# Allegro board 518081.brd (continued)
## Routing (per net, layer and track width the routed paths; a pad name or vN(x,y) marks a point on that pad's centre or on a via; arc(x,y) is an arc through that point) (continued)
MII0_TXP1: length 18.4
  TOP w0.104: P0.1 19.23,11.37 19.23,11.96 19.34,12.06 21.66,12.06 26.16,16.57 26.16,19.56 26.57,19.97 27.4,19.97 R12.1 28.6,20.09 29.77,20.09 29.93,19.94 U6.12
MII1_RXM1: length 15.5
  TOP w0.104: U3.9 29.69,36.68 28.68,37.68 28.48,37.68 R2.1 27.41,37.7 26,37.7 25.05,38.64 21.88,38.64 21.56,38.96 18.96,38.96 18.57,38.58 18.57,38.25 18.41,38.1 17.91,38.1 P1.8
MII1_RXP1: length 15.2
  TOP w0.104: U3.10 29.86,36.18 28.59,37.45 28.44,37.45 R3.1 27.43,37.47 25.9,37.47 24.96,38.41 21.78,38.41 21.46,38.73 19.05,38.73 18.8,38.48 18.8,37.85 19.18,37.47 P1.7
MII1_TXM1: length 15.8
  TOP w0.104: P1.2 17.65,30.73 18.8,30.73 19.3,31.24 21.77,31.24 25.97,35.44 27.44,35.44 R4.1 28.32,35.56 29.81,35.56 29.93,35.68 U3.11
MII1_TXP1: length 15
  TOP w0.104: U3.12 29.93,35.18 29.77,35.33 28.6,35.33 R5.1 27.4,35.21 26.07,35.21 21.87,31.01 19.4,31.01 19.23,30.85 19.23,30.42 P1.1
P_CONF[2]: length 5.2
  TOP w0.305: U5.E3 v2(53.67,28.6)
  BOTTOM w0.127: v2(53.67,28.6) 54.06,28.99 54.78,28.99 55.24,29.46 55.24,30.35 55.88,30.99 R20.1
PFBOUT0: length 7.9
  TOP w0.254: v2(29.21,18.19) 29.22,18.21 29.35,18.21 29.58,18.43 U6.15 ; U6.13 29.72,19.43 29.47,19.68 v2(29.46,19.68)
  TOP w0.305: v2(34.92,16.13) 34.9,16.15 U6.24
  BOTTOM w0.305: v2(34.92,16.13) 35.05,16.26 C71.1 ; C74.1 28.75,18.21 29.2,18.21 v2(29.21,18.19) 29.37,18.19 29.4,18.16 C70.1 ; C59.1 29.88,20.19 29.46,19.78 v2(29.46,19.68)
PFBOUT1: length 7.6
  TOP w0.254: v2(29.46,34.92) 29.47,34.92 29.72,34.67 U3.13 ; U3.15 29.58,33.67 29.31,33.4 v2(29.21,33.4)
  TOP w0.305: v2(35.05,31.46) 34.9,31.61 U3.24
  BOTTOM w0.254: C21.1 v2(29.21,33.4)
  BOTTOM w0.305: C23.1 v2(35.05,31.46) ; C16.1 29.97,35.43 v2(29.46,34.92) ; C26.1 28.87,33.45 29.17,33.45 v2(29.21,33.4)
PHYAD_OFF: length 4.6
  TOP w0.305: U5.C3 v2(55.27,28.6)
  BOTTOM w0.127: v2(55.27,28.6) 55.66,28.99 55.66,29.76 57.15,31.24 R18.1
PR2_MDIO_DATA: length 45
  TOP w0.127: U6.19 32.4,15.48 33.53,14.35 v1(36.32,14.35) 37.97,14.35 38.61,13.72 45.01,13.72 45.91,14.62 v1(46.35,14.62) 46.35,15.24 47.75,16.64 47.75,17.78 48.77,18.8 48.77,20.07 49.27,20.57 U5.K12 ; U3.19 32.4,31.66 32,31.27 v2(32,27.05)
  BOTTOM w0.127: v1(36.32,14.35) 36.32,14.86 36.2,14.99 36.2,20.83 32,25.02 v2(32,27.05) ; v1(46.35,14.62) R68.1
PR2_MDIO_MDCLK: length 45.1
  TOP w0.127: U5.K11 48.87,21.4 48.87,20.57 48.62,20.32 48.13,20.32 46.74,18.92 v1(44.95,18.92) 44.95,16.62 42.42,14.1 38.86,14.1 37.97,14.99 v1(36.83,14.99) 36.45,15.37 33.03,15.37 32.7,15.69 32.7,16.06 32.9,16.25 U6.20 ; U3.20 32.9,31.63 32.51,31.24 v2(32.51,26.54)
  BOTTOM w0.127: v1(36.83,14.99) 36.52,15.3 36.52,21.14 32.51,25.15 v2(32.51,26.54) ; v1(44.95,18.92) R60.1 R59.1
PR2_MII0_LINKACT: length 36.9
  TOP w0.127: v1(37.47,13.21) 47.23,13.21 v1(48.64,14.62) 48.64,15.37 50.07,16.8 U5.J12
  BOTTOM w0.127: v1(37.47,13.21) 36.2,11.94 29.46,11.94 27.56,13.84 26.54,13.84 24.64,15.75 P0.11 ; v1(48.64,14.62) R66.1
PR2_MII0_RXCLK: length 18.4
  TOP w0.127: U6.25 36.55,17.93 37.34,17.14 38.48,17.14 39.12,16.51 41.53,16.51 v1(42.29,17.27) ; U5.L10 48.07,22.2 47.22,22.2 46.74,21.72 v1(42.55,21.72)
  L4_ROUTE w0.127: v1(42.55,21.72) 42.55,19.81 42.67,19.68 42.67,18.67 42.29,18.29 v1(42.29,17.27)
PR2_MII0_RXD0: length 18.7
  TOP w0.127: v2(39.24,20.32) 37.72,20.32 37.6,20.44 U6.30
  TOP w0.305: U5.K10 v2(48.87,22.2)
  BOTTOM w0.127: v2(48.87,22.2) 47.52,22.2 46.99,22.73 42.93,22.73 42.51,23.15 39.03,23.15 38.57,22.69 R53.2 v2(39.24,20.32) R52.1
PR2_MII0_RXD1: length 13.8
  TOP w0.127: v2(39.24,21.08) 38.82,21.08 38.68,20.94 U6.31 ; U5.M12 46.61,19.94 43.94,19.94 v1(43.69,19.68)
  L3_ROUTE w0.127: v1(43.69,19.68) 40.64,19.68 v2(39.24,21.08)
  BOTTOM w0.127: R50.1 v2(39.24,21.08)
PR2_MII0_RXD2: length 14.8
  TOP w0.127: v2(39.24,21.84) 38.84,21.44 U6.32 ; v1(43.18,20.32) 46.35,20.32 47.43,21.4 48.07,21.4 U5.L11
  L3_ROUTE w0.127: v2(39.24,21.84) 40.77,20.32 v1(43.18,20.32)
  BOTTOM w0.127: R49.1 v2(39.24,21.84)
PR2_MII0_RXD3: length 17.3
  TOP w0.127: v1(42.04,19.05) 44.2,19.05 44.7,19.56 46.86,19.56 47.95,20.65 48.12,20.65 U5.L12 ; U6.1 37.87,22.25 38.35,22.73 v2(39.24,22.73)
  L4_ROUTE w0.127: v2(39.24,22.73) 42.04,19.94 v1(42.04,19.05)
  BOTTOM w0.127: v2(39.24,22.73) 39.37,22.61 R48.1
PR2_MII0_RXDV: length 17.8
  TOP w0.127: U6.26 36.69,18.43 37.55,17.57 38.95,17.57 v2(39.24,17.27) 43.43,21.46 46.98,21.46 47.32,21.8 U5.M11
  BOTTOM w0.127: TP12.1 v2(39.24,17.27) ; v2(39.24,17.27) R63.1 ; v2(39.24,17.27) R64.2
PR2_MII0_RXER: length 15.6
  TOP w0.127: U5.M10 46.87,22.6 46.8,22.67 42.35,22.67 41.66,21.97 41.66,21.21 v2(39.24,18.8) 37.59,18.8 36.95,19.43 U6.28
  BOTTOM w0.127: R56.1 v2(39.24,18.8) R57.2
PR2_MII0_RXLINK: length 40.7
  TOP w0.127: U6.17 v1(31.39,13.44) 29.44,13.44 TP14.1 27.94,12.32 24.64,12.32 ; v1(37.72,22.86) 38.03,23.17 39.56,23.17 39.74,23 48.07,23 U5.L9
  BOTTOM w0.127: v1(37.72,22.86) 37.72,21.84 37.44,21.56 37.44,16.28 37.85,15.87 37.85,14.35 35.81,12.32 32.51,12.32 v1(31.39,13.44) ; R69.2 24.64,12.32
PR2_MII0_TXD0: length 19.9
  TOP w0.127: v1(39.62,24.13) 37.59,26.16 34.54,26.16 33.4,25.02 U6.4
  TOP w0.305: U5.L8 v2(48.07,23.8)
  BOTTOM w0.127: v2(48.07,23.8) 46.94,23.8 46.74,24 43.31,24 43.18,24.13 R47.1 41.91,23.62 40.13,23.62 v1(39.62,24.13)
PR2_MII0_TXD1: length 19.2
  TOP w0.127: U6.5 32.9,25.02 34.42,26.54 37.59,26.54 39.37,24.77 42.16,24.77 42.67,24.26 46.61,24.26 46.73,24.14 47.26,24.14 47.32,24.2 U5.M8
PR2_MII0_TXD2: length 21.6
  TOP w0.127: v1(39.62,25.27) 37.97,26.92 34.29,26.92 32.4,25.03 U6.6
  TOP w0.305: U5.L7 v2(48.07,24.6)
  BOTTOM w0.127: v1(39.62,25.27) 40.13,24.77 41.91,24.77 R46.1 43.43,24.26 46.86,24.26 46.99,24.13 47.6,24.13 v2(48.07,24.6)
PR2_MII0_TXD3: length 21.2
  TOP w0.127: v1(39.62,26.29) 38.61,27.3 34.16,27.3 31.89,25.04 U6.7
  TOP w0.305: U5.M7 v2(47.27,24.6)
  BOTTOM w0.127: v1(39.62,26.29) 40.01,25.91 41.91,25.91 R45.1 43.43,25.4 46.47,25.4 v2(47.27,24.6)
PR2_MII0_TXEN: length 17.1
  TOP w0.127: U5.M9 47.11,23.4 46.57,23.94 43.5,23.94 43.05,23.5 39.5,23.5 37.97,25.02 TP10.1 33.9,24.12 U6.3
PR2_MII1_LINKACT: length 33.8
  TOP w0.127: v1(46.86,34.54) 47.37,34.04 47.37,32.64 48.47,31.54 U5.L1
  BOTTOM w0.127: P1.11 25.4,36.45 26.54,36.45 26.8,36.7 35.81,36.7 36.83,35.69 36.83,32.64 37.53,31.94 43.88,31.94 46.48,34.54 v1(46.86,34.54) R25.1
PR2_MII1_RXCLK: length 18.1
  TOP w0.127: v1(38.23,28.19) 38.23,29.21 36.83,30.61 36.83,32.77 36.42,33.17 U3.25
  TOP w0.305: U5.K4 v2(48.87,27.8)
  BOTTOM w0.127: v1(38.23,28.19) 38.54,28.51 42.36,28.51 43.05,27.81 48.48,27.81 48.49,27.8 v2(48.87,27.8)
PR2_MII1_RXD0: length 19.1
  TOP w0.127: U5.L4 48.07,27.8 45.73,27.8 44.83,28.7 44.83,30.23 41.15,33.91 41.15,34.29 v2(39.24,36.2) 38.35,36.2 37.84,35.68 U3.30
  BOTTOM w0.127: R22.1 v2(39.24,36.2) R23.2
PR2_MII1_RXD1: length 23.5
  TOP w0.127: v2(39.24,36.96) 38.35,36.96 37.57,36.18 U3.31 ; v1(40.13,27.69) 40.77,27.69 42.93,25.53 46.6,25.53 U5.M5
  L4_ROUTE w0.127: v2(39.24,36.96) 38.73,36.45 38.73,32.64 40.13,31.24 v1(40.13,27.69)
  BOTTOM w0.127: R17.1 v2(39.24,36.96)
PR2_MII1_RXD2: length 23.5
  TOP w0.127: v2(39.24,37.72) 38.48,37.72 37.44,36.68 U3.32 ; U5.L5 48.07,27 47.45,27 46.99,26.54 42.42,26.54 41.15,27.81 41.15,29.46 v1(40.77,29.84)
  L4_ROUTE w0.127: v2(39.24,37.72) 39.88,37.08 39.88,32.13 40.77,31.24 v1(40.77,29.84)
  BOTTOM w0.127: R16.1 v2(39.24,37.72)
PR2_MII1_RXD3: length 26.8
  TOP w0.127: U5.M6 47.14,25.27 42.29,25.27 41.53,26.04 41.53,26.42 40.89,27.05 40.01,27.05 v1(39.12,27.94) ; v2(39.24,38.48) 38.48,38.48 37.49,37.49 U3.1
  L4_ROUTE w0.127: v1(39.12,27.94) 39.12,28.83 38.35,29.59 38.35,37.59 v2(39.24,38.48)
  BOTTOM w0.127: R15.1 v2(39.24,38.48)
PR2_MII1_RXDV: length 19
  TOP w0.127: v1(42.29,30.1) 43.18,29.21 43.18,27.05 43.43,26.8 46.71,26.8 47.32,27.4 U5.M4 ; TP8.1 v2(39.24,33.15) 37.08,33.15 36.56,33.67 U3.26
  BOTTOM w0.127: v1(42.29,30.1) 41.53,30.86 TP8.1 ; R38.2 v2(39.24,33.15) R37.1
PR2_MII1_RXER: length 20.1
  TOP w0.127: v1(42.67,27.3) 41.53,28.45 41.53,30.23 39.88,31.88 39.88,34.04 v2(39.24,34.67) 36.7,34.67 36.7,34.67 U3.28
  TOP w0.305: U5.L6 v2(48.07,26.2)
  BOTTOM w0.127: v2(48.07,26.2) 47.21,26.2 46.74,26.67 43.31,26.67 v1(42.67,27.3) ; R32.2 v2(39.24,34.67) R31.1
PR2_MII1_RXLINK: length 33.9
  TOP w0.127: P1.10 26.8,29.21 TP9.1 v1(30.99,29.21) 30.99,31.25 31.39,31.66 U3.17
  TOP w0.305: U5.K3 v2(48.87,28.6)
  BOTTOM w0.127: P1.10 25.65,30.35 25.65,29.97 26.42,29.21 R41.2 ; v1(30.99,29.21) 32.38,27.81 35.69,27.81 37.08,29.21 46.48,29.21 47.09,28.6 v2(48.87,28.6)
PR2_MII1_TXD0: length 25.8
  TOP w0.127: U3.4 33.4,38.86 35.56,41.02 38.1,41.02 43.43,35.69 v1(43.43,34.54) 43.43,32.96 45.85,30.54 45.85,29.46 46.23,29.08 46.61,29.08 47.09,28.6 48.07,28.6 U5.L3
  BOTTOM w0.127: v1(43.43,34.54) R28.1
PR2_MII1_TXD1: length 24.4
  TOP w0.127: U5.M2 47.32,29 46.86,29.45 46.86,30.23 43.94,33.15 43.94,35.81 38.35,41.4 35.31,41.4 32.9,38.99 U3.5
PR2_MII1_TXD2: length 27.7
  TOP w0.127: U3.6 32.4,39 35.18,41.78 39.88,41.78 44.07,37.59 44.07,36.2 44.58,35.69 v1(44.58,34.54) 44.58,33.02 47.12,30.48 47.12,29.72 47.43,29.4 48.07,29.4 U5.L2
  BOTTOM w0.127: R27.1 v1(44.58,34.54)
PR2_MII1_TXD3: length 27.7
  TOP w0.127: U5.M1 47.67,30.44 45.72,32.38 v1(45.72,34.54) 45.72,35.69 45.21,36.2 45.21,37.59 40.64,42.16 35.05,42.16 31.89,39.01 U3.7
  BOTTOM w0.127: v1(45.72,34.54) R26.1
PR2_MII1_TXEN: length 23.1
  TOP w0.127: U3.3 33.9,38.72 35.31,40.13 TP1.1 38.35,40.13 42.93,35.56 42.93,32.89 45.47,30.35 45.47,28.84 46.23,28.07 47.18,28.07 47.32,28.2 U5.M3
PR2_MII_RESETN: length 56.8
  TOP w0.127: v1(30.48,23.62) 30.48,27.69 31.5,28.7 31.5,31.24 31.89,31.64 U3.18 ; U6.18 31.89,15.22 33.15,13.97 35.81,13.97 v1(36.2,13.59) 37.08,12.7 v1(43.81,12.7) 47.75,12.7 49.09,14.03 49.09,15.3 50.32,16.54 50.32,20.45 U5.H12 ; v1(43.81,8.89) 44.17,8.53 U1.4
  BOTTOM w0.127: v1(43.81,8.89) v1(43.81,12.7) ; v1(30.48,23.62) 32.77,23.62 35.81,20.57 35.81,13.97 v1(36.2,13.59)
PR2_MII_XI: length 44.4
  TOP w0.127: U6.23 34.4,16.02 34.77,15.65 36.22,15.65 36.45,15.88 v1(37.08,15.88) 41.15,15.88 TP13.1 ; U3.23 34.4,31.01 v1(37.21,28.19)
  TOP w0.305: U5.F2 v2(52.87,29.4)
  BOTTOM w0.127: v1(37.08,15.88) 37.08,16.32 36.96,16.44 36.96,23.24 37.21,23.5 v1(37.21,28.19) 37.97,28.96 42.67,28.96 43.56,28.07 47.75,28.07 47.89,28.21 51.43,28.21 51.66,28.44 51.66,28.45 51.79,28.57 52.04,28.57 v2(52.87,29.4)
REG_5V_IN: length 2.9
  TOP w0.305: J10.2 52.16,8.47 ; J10.2 52.16,6.51 ; J10.2 53.14,7.49
N21750864: length 5
  TOP w0.127: v2(39.24,19.56) 37.59,19.56 37.21,19.94 U6.29
  BOTTOM w0.127: R55.2 v2(39.24,19.56) R54.1
N21750872: length 5.2
  TOP w0.127: U6.27 36.82,18.93 37.72,18.03 v2(39.24,18.03)
  BOTTOM w0.127: R62.2 v2(39.24,18.03) R61.1
N21750878: length 3.7
  TOP w0.127: U6.16 30.58,16.74 v2(29.97,16.13)
  BOTTOM w0.127: R65.1 v2(29.97,16.13)
N21751363: length 1.7
  BOTTOM w0.127: R74.1 P0.9
N21751679: length 15.1
  BOTTOM w0.305: P0.5 19.81,16.78 ; P0.5 19.81,14.97 ; P0.5 20.71,15.88 ; P0.5 18.91,15.88 ; P0.14 13.97,8.69 ; P0.14 15.29,7.37 ; P0.14 12.65,7.37 ; 16.37,14.61 P0.4 ; P0.4 18.17,14.61 ; P0.4 17.27,13.7 ; P0.4 17.27,15.51 ; 12.65,23.11 P0.13 ; P0.13 13.97,21.79 ; P0.13 15.29,23.11
N21752228: length 3.4
  TOP w0.127: R8.2 31.11,23.62 31.39,23.34 U6.8
N21760792: length 5
  TOP w0.127: v2(39.24,35.43) 38.35,35.43 38.1,35.18 U3.29
  BOTTOM w0.127: R29.1 v2(39.24,35.43) R30.2
N21760889: length 5
  TOP w0.127: v2(39.24,33.91) 37.21,33.91 36.95,34.17 U3.27
  BOTTOM w0.127: R36.2 v2(39.24,33.91) R35.1
N21760945: length 2.3
  BOTTOM w0.127: P1.9 25.53,27.94 R43.1
N21760963: length 15.1
  BOTTOM w0.305: P1.4 17.27,34.56 ; P1.4 18.17,33.66 ; P1.4 17.27,32.75 ; P1.4 16.37,33.66 ; P1.14 15.29,26.42 ; P1.14 12.65,26.42 ; P1.14 13.97,27.74 ; 13.97,40.84 P1.13 ; P1.13 15.29,42.16 ; P1.13 12.65,42.16 ; P1.5 19.81,35.83 ; P1.5 19.81,34.02 ; P1.5 20.71,34.92 ; P1.5 18.91,34.92
N21761103: length 3.7
  TOP w0.127: v2(29.97,31.37) 30.58,31.98 U3.16
  BOTTOM w0.127: R40.1 v2(29.97,31.37)
N21761294: length 3.6
  TOP w0.127: U3.8 31.39,39.01 32.26,39.88 32.26,40.77
N21764803: length 12.2
  TOP w0.127: C7.1 52.53,10.87 Y1.1 53.37,11.94 53.59,12.17 53.59,15.88 52.7,16.76 52.7,20.19 52.47,20.43 U5.F12
N21764807: length 7.2
  TOP w0.127: Y1.3 50.6,15.29 C3.1 51.05,16.38 51.44,16.76 51.44,20.07 51.67,20.3 U5.G12
N21767563: length 5.9
  TOP w0.305: U5.C4 v2(55.27,27.8)
  BOTTOM w0.127: v2(55.27,27.8) 56.48,29.01 56.48,29.93 R19.1
N21781367: length 4.3
  TOP w0.127: U3.2 34.4,38.19 34.67,38.46 37.31,38.46 TP7.1
N21781382: length 4.5
  TOP w0.127: TP11.1 35.45,24 34.4,22.95 U6.2
N21785424: length 2.2
  TOP w0.127: DS1.1 v1(37.07,11.43)
  BOTTOM w0.127: v1(37.07,11.43) R72.2
N21788279: length 1.7
  BOTTOM w0.127: R14.1 P1.12
N21789027: length 1.7
  BOTTOM w0.127: R51.1 P0.12
N21791162: length 13.8
  TOP w0.127: TP4.1 50.8,41.02 v1(51.44,40.39) 51.94,39.88 51.94,34.67 52.58,34.04 52.58,30.61 52.47,30.5 U5.F1
  BOTTOM w0.127: v1(51.44,40.39) R21.2
N21791165: length 12.7
  TOP w0.127: U5.E1 52.83,30.24 52.83,34.29 52.3,34.82 52.3,41.51 TP5.1
N21791168: length 13.4
  TOP w0.127: TP2.1 47.5,41.4 47.5,34.67 47.88,34.29 47.88,33.53 50.07,31.34 U5.J1
N21791171: length 13.8
  TOP w0.127: U5.H1 50.36,30.31 50.36,31.81 48.39,33.78 48.39,34.42 47.88,34.92 47.88,40.89 TP3.1
N21791186: length 14
  TOP w0.127: TP6.1 52.7,40.01 52.7,35.18 53.98,33.91 53.98,32.77 55.12,31.62 55.12,30.86 54.87,30.61 U5.C1
N21791230: length 14
  TOP w0.305: U5.A4 v2(56.87,27.8) ; U5.C10 v2(55.27,22.2)
  L4_ROUTE w0.127: v2(56.87,27.8) 56.48,27.41 55.12,27.41 54.86,27.15 54.86,22.61 v2(55.27,22.2)
  BOTTOM w0.127: v2(56.87,27.8) 57.25,27.8 57.39,27.94 60.45,27.94 R39.2
N21823994: length 3.9
  TOP w0.305: J3.3 70.04,13.93 ; J3.3 71.02,12.95 ; J3.3 70.04,11.98 ; J3.3 69.06,12.95
N21833989: length 6.4
  BOTTOM w0.127: J6.54 60.81,41.55 60.33,42.04 58.67,42.04 57.15,40.51 R7.1
N21833992: length 2.1
  BOTTOM w0.127: J6.55 60.41,36.4 60.33,36.32 60.33,36.07 60.07,35.81 59.82,35.81 R6.2
N21843407: length 22.4
  TOP w0.127: SW1.4 v1(71.75,33.02) ; U7.1 v1(68.71,15.5)
  L4_ROUTE w0.127: v1(68.71,15.5) 69.85,16.65 69.85,21.84 70.61,22.61 70.61,31.88 v1(71.75,33.02)
  BOTTOM w0.127: R33.1 v1(71.75,33.02)
N21843411: length 19
  TOP w0.127: U2.19 65.73,23.18 65.86,23.3 67.75,23.3 69.21,21.84 v1(70.48,21.84) ; v1(71.75,31.75) SW1.3
  L4_ROUTE w0.127: v1(70.48,21.84) 70.99,22.35 70.99,30.99 v1(71.75,31.75)
  BOTTOM w0.127: R34.1 v1(71.75,31.75)
N21843710: length 2.5
  TOP w0.127: v1(62.87,16.51) 63.22,16.15 U7.15
  BOTTOM w0.127: R58.2 v1(62.87,16.51)
N21870681: length 7.4
  L3_ROUTE w0.305: 53.26,7.49 J10.3 ; J10.3 54.16,6.59 ; J10.3 54.16,8.4 ; J10.3 55.07,7.49 ; J9.1 72.84,8.26 ; J9.1 71.88,7.3 ; J9.1 70.93,8.26 ; J9.1 71.88,9.21
N21871502: length 2.2
  TOP w0.127: DS2.1 v1(37.07,8.64)
  BOTTOM w0.127: v1(37.07,8.64) R75.2

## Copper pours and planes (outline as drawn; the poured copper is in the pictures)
GND on BOTTOM: 30.73,20.7 30.73,16.89 30.99,16.64 31.62,16.64 31.88,16.89 31.88,17.65 32.13,17.91 35.31,17.91 35.56,18.16 35.56,19.94 35.37,20.13 35.43,20.19 34.42,21.21 31.24,21.21
GND on BOTTOM: 30.73,35.94 30.73,32.13 30.99,31.88 31.62,31.88 31.88,32.13 31.88,32.89 32.13,33.15 35.43,33.15 35.94,33.66 35.94,35.56 35.05,36.45 31.24,36.45
GND on L2_GND: 78.11,6.35 0.64,6.35 0.64,43.18 78.11,43.18
VCC_2V5 on L3_ROUTE: 45.47,27.81 45.47,21.97 48.39,19.05 51.94,19.05 52.58,19.68 52.58,21.08 55.75,24.26 55.75,27.43 54.61,28.57 46.23,28.57
VCC_2V5 on L4_ROUTE: 55.12,26.42 55.12,23.37 55.63,22.86 60.71,22.86 62.1,24.26 62.1,26.67 60.45,28.32 58.04,28.32 56.77,27.05 55.75,27.05
VCC_3V3 on TOP: 58.29,41.66 58.29,36.32 59.56,35.05 70.87,35.05 72.39,33.53 72.39,11.43 77.85,11.43 77.85,40.64 76.83,41.66
EVM_3V3 on L5_PWR: 0.64,6.35 0.64,43.18 78.11,43.18 78.11,6.35
PFBOUT0 on L3_ROUTE: 27.3,20.95 27.3,16.51 29.84,13.97 34.29,13.97 36.2,15.88 36.2,19.68 34.29,21.59 27.94,21.59
PFBOUT1 on L3_ROUTE: 27.3,36.2 27.3,31.75 29.84,29.21 34.29,29.21 36.2,31.11 36.2,34.92 34.29,36.83 27.94,36.83
REG_5V_IN on TOP: 51.31,9.27 51.31,6.22 57.02,6.22 57.66,6.86 57.66,8.51 57.4,8.76 56.26,8.76 55.5,9.53 51.56,9.53
N21751679 on BOTTOM: 16,15.88 17.91,15.88 19.18,17.14 21.08,17.14 21.08,14.61 19.18,14.61 17.91,13.34 16,13.34 16,10.67 17.27,9.4 17.27,6.91 16.98,6.62 9,6.62 8.13,7.49 8.13,23.11 9.27,24.26 15.37,24.26 16,23.62
N21760963 on BOTTOM: 16,34.92 17.91,34.92 19.18,36.2 21.08,36.2 21.08,33.66 19.18,33.66 17.91,32.38 16,32.38 16,30.48 17.27,29.21 17.27,26.54 16.51,25.78 8.89,25.78 8.13,26.54 8.13,42.16 9.27,43.31 15.24,43.31 16,42.55
N21823994 on TOP: 64.9,14.61 64.64,14.35 64.64,13.34 64.26,12.95 63.75,12.95 63.12,12.32 62.36,12.32 62.1,12.06 62.1,10.29 70.48,10.29 71.37,11.18 71.37,14.1 70.87,14.61
N21823999 on TOP: 62.1,9.27 62.61,9.27 62.87,9.02 62.87,8 63.63,7.24 67.56,7.24 67.82,7.49 67.82,9.4 67.44,9.78 62.1,9.78
N21824161 on TOP: 60.83,10.41 59.69,10.41 59.44,10.16 59.44,9.91 59.69,9.65 60.83,9.65 60.83,8.64 61.59,7.87 61.59,7.49 61.34,7.24 58.55,7.24 58.29,7.49 58.29,13.08 58.55,13.34 60.07,13.34 60.83,12.57
N21870681 on L3_ROUTE: 52.2,10.41 52.2,6.48 52.32,6.35 73.66,6.35 74.42,7.11 74.42,11.68 73.28,12.83 54.61,12.83

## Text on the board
BOTTOM: SOLDER | LAYER 6
Board Geometry/Soldermask Bottom: SMS
Ref Des/Silkscreen Bottom: NOT FCC APPROVED FOR RESALE | FOR EVALUATION ONLY; | S/N | ASSY 518080 REV | PWB 518081 REV B | LOGIC 518082 REV B | BSLK
TOP: COMPONENT | LAYER 1
Board Geometry/Soldermask Top: SMC
Ref Des/Silkscreen Top: PORT1-OUT | PORT0-IN | C2000-ET1100 ADAPTER BOARD | VCC5V | Ex5V | GND | RUN | 1 | INT | 3V3 | EXT | SPI | EMIF | TSLK
L2_GND: LAYER 2 | GND
L3_ROUTE: LAYER 3
L4_ROUTE: LAYER 4
L5_PWR: PWR | LAYER 5
USER_PART_NUM_TOP: TSLKC
DIMENSION: DRILL
USER_PART_NUM_BOTTOM: BSLKC
DISPLAY_BOTTOM: SPS
DISPLAY_TOP: SPC
User.19: SCORE LINE, 2 PLCS. | DATE | DESIGN ENGR | PROJECT ENGR | ENGR MGR | NEXT ASSEMBLY | APPROVED | CHECKED | DRAFTING | ENGR | NONE | 1 OF 1 | NOTES: UNLESS OTHERWISE SPECIFIED | 1   TOTAL BOARD THICKNESS SHALL BE .062 +/- .007 INCHES. | 4.  SOLDERMASK ON BOTH SIDES OF THE BOARD SHALL BE S.M.O.B.C., LPI, COLOR GREEN. | 3.  MINIMUM TRACE AND SPACE SHALL BE .005 OF AN INCH. | 2.  COPPER PLATED SURFACE CONDUCTORS SHALL BE THE EQUIVALENT OF 1 OZ. COPPER | 6.  FINISHED BOARD SHALL BE FREE OF BURRS ON EDGES. | 5.  PLATED THRU HOLE SIZE TOLERANCES SHALL BE +/- .003 INCH. | 9.  IMPEDENCE CONTROL: | 7.  SURFACE FINISH SHALL BE IMMERSION GOLD. | 8.  5 MIL WIDTH TRACES TO BE CONTROLLED IMPEDANCE,50 OHMS SINGLE ENDED ON ALL ROUTING LAYERS. | AFTER PLATING.  PLANE LAYERS SHALL BE 1 OZ. COPPER.  AVERAGE COPPER ON | THE WALL OF THE PLATED HOLE SHALL BE .001 INCH. | ALL MATERIAL SHALL BE NEMA GRADE FR-4 OR EQUIVALENT. (Tg>=170 DEG. C) | UNPLATED THRU HOLE SIZE TOLERANCES SHALL BE +/- .002 INCH. | 100 OHM DIFFERENTIAL +/-10% 4.1 MIL TRACE.
User.20: DATE | DESIGN ENGR | PROJECT ENGR | ENGR MGR | NEXT ASSEMBLY | APPROVED | CHECKED | DRAFTING | ENGR | 1 OF 1
User.23: 1. All board outlines shall be .020 in width. | 2. All other lines shall be .012 in width. | 3. Note and misc. text shall be text block 10. | 4. View and description text shall be text block 16. | 5. Make sure that there is not any double dimensioning, | 6. Check all notes to make sure that they apply and are correct. | 7. Make sure that layer stack-up is correct. | label (REF) dim when needed.
User.26: FIGURE | SIZE | 8.0 | 10.0 | 12.0 | 20.0 | 35.0 | 38.0 | 40.0 | 64.0 | 98.0 | 128.0 | DRILL CHART: TOP to BOTTOM | ALL UNITS ARE IN MILS | PLATED | NON-PLATED | QTY | 106 | 306 | 2 | 4 | 6 | 22 | 1 | 3
